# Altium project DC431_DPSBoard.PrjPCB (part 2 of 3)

## Sheet DC431_ADC.SchDoc
size C; Date: Not shown in title block; ApprovedBy: Not shown in title block; CheckedBy: Not shown in title block; Author: Not shown in title block; CompanyName: Not shown in title block; DrawnBy: Battery test; Engineer: Not shown in title block; Organization: Not shown in title block; Address1: Not shown in title block; Address2: Not shown in title block; Address3: Not shown in title block; Address4: Not shown in title block; DocumentNumber: 5; Revision: Use project parameter SCH_Rev; SheetNumber: 6; SheetTotal: 9; PageSetup: Record=PageOptions¦CenterHorizontal=True¦CenterVertical=True¦PrintScale=1.00¦XCorrection=1.00¦YCorrection=1.00¦PrintKind=0¦BorderSize=5000000¦LeftOffset=0¦BottomOffset=0¦Orientation=2¦PaperLength=1000¦PaperWidth=1000¦Scale=100¦PaperSource=15¦PrintQuality=600¦MediaType=1¦DitherType=10¦PaperKind=Letter¦PrintScaleMode=1
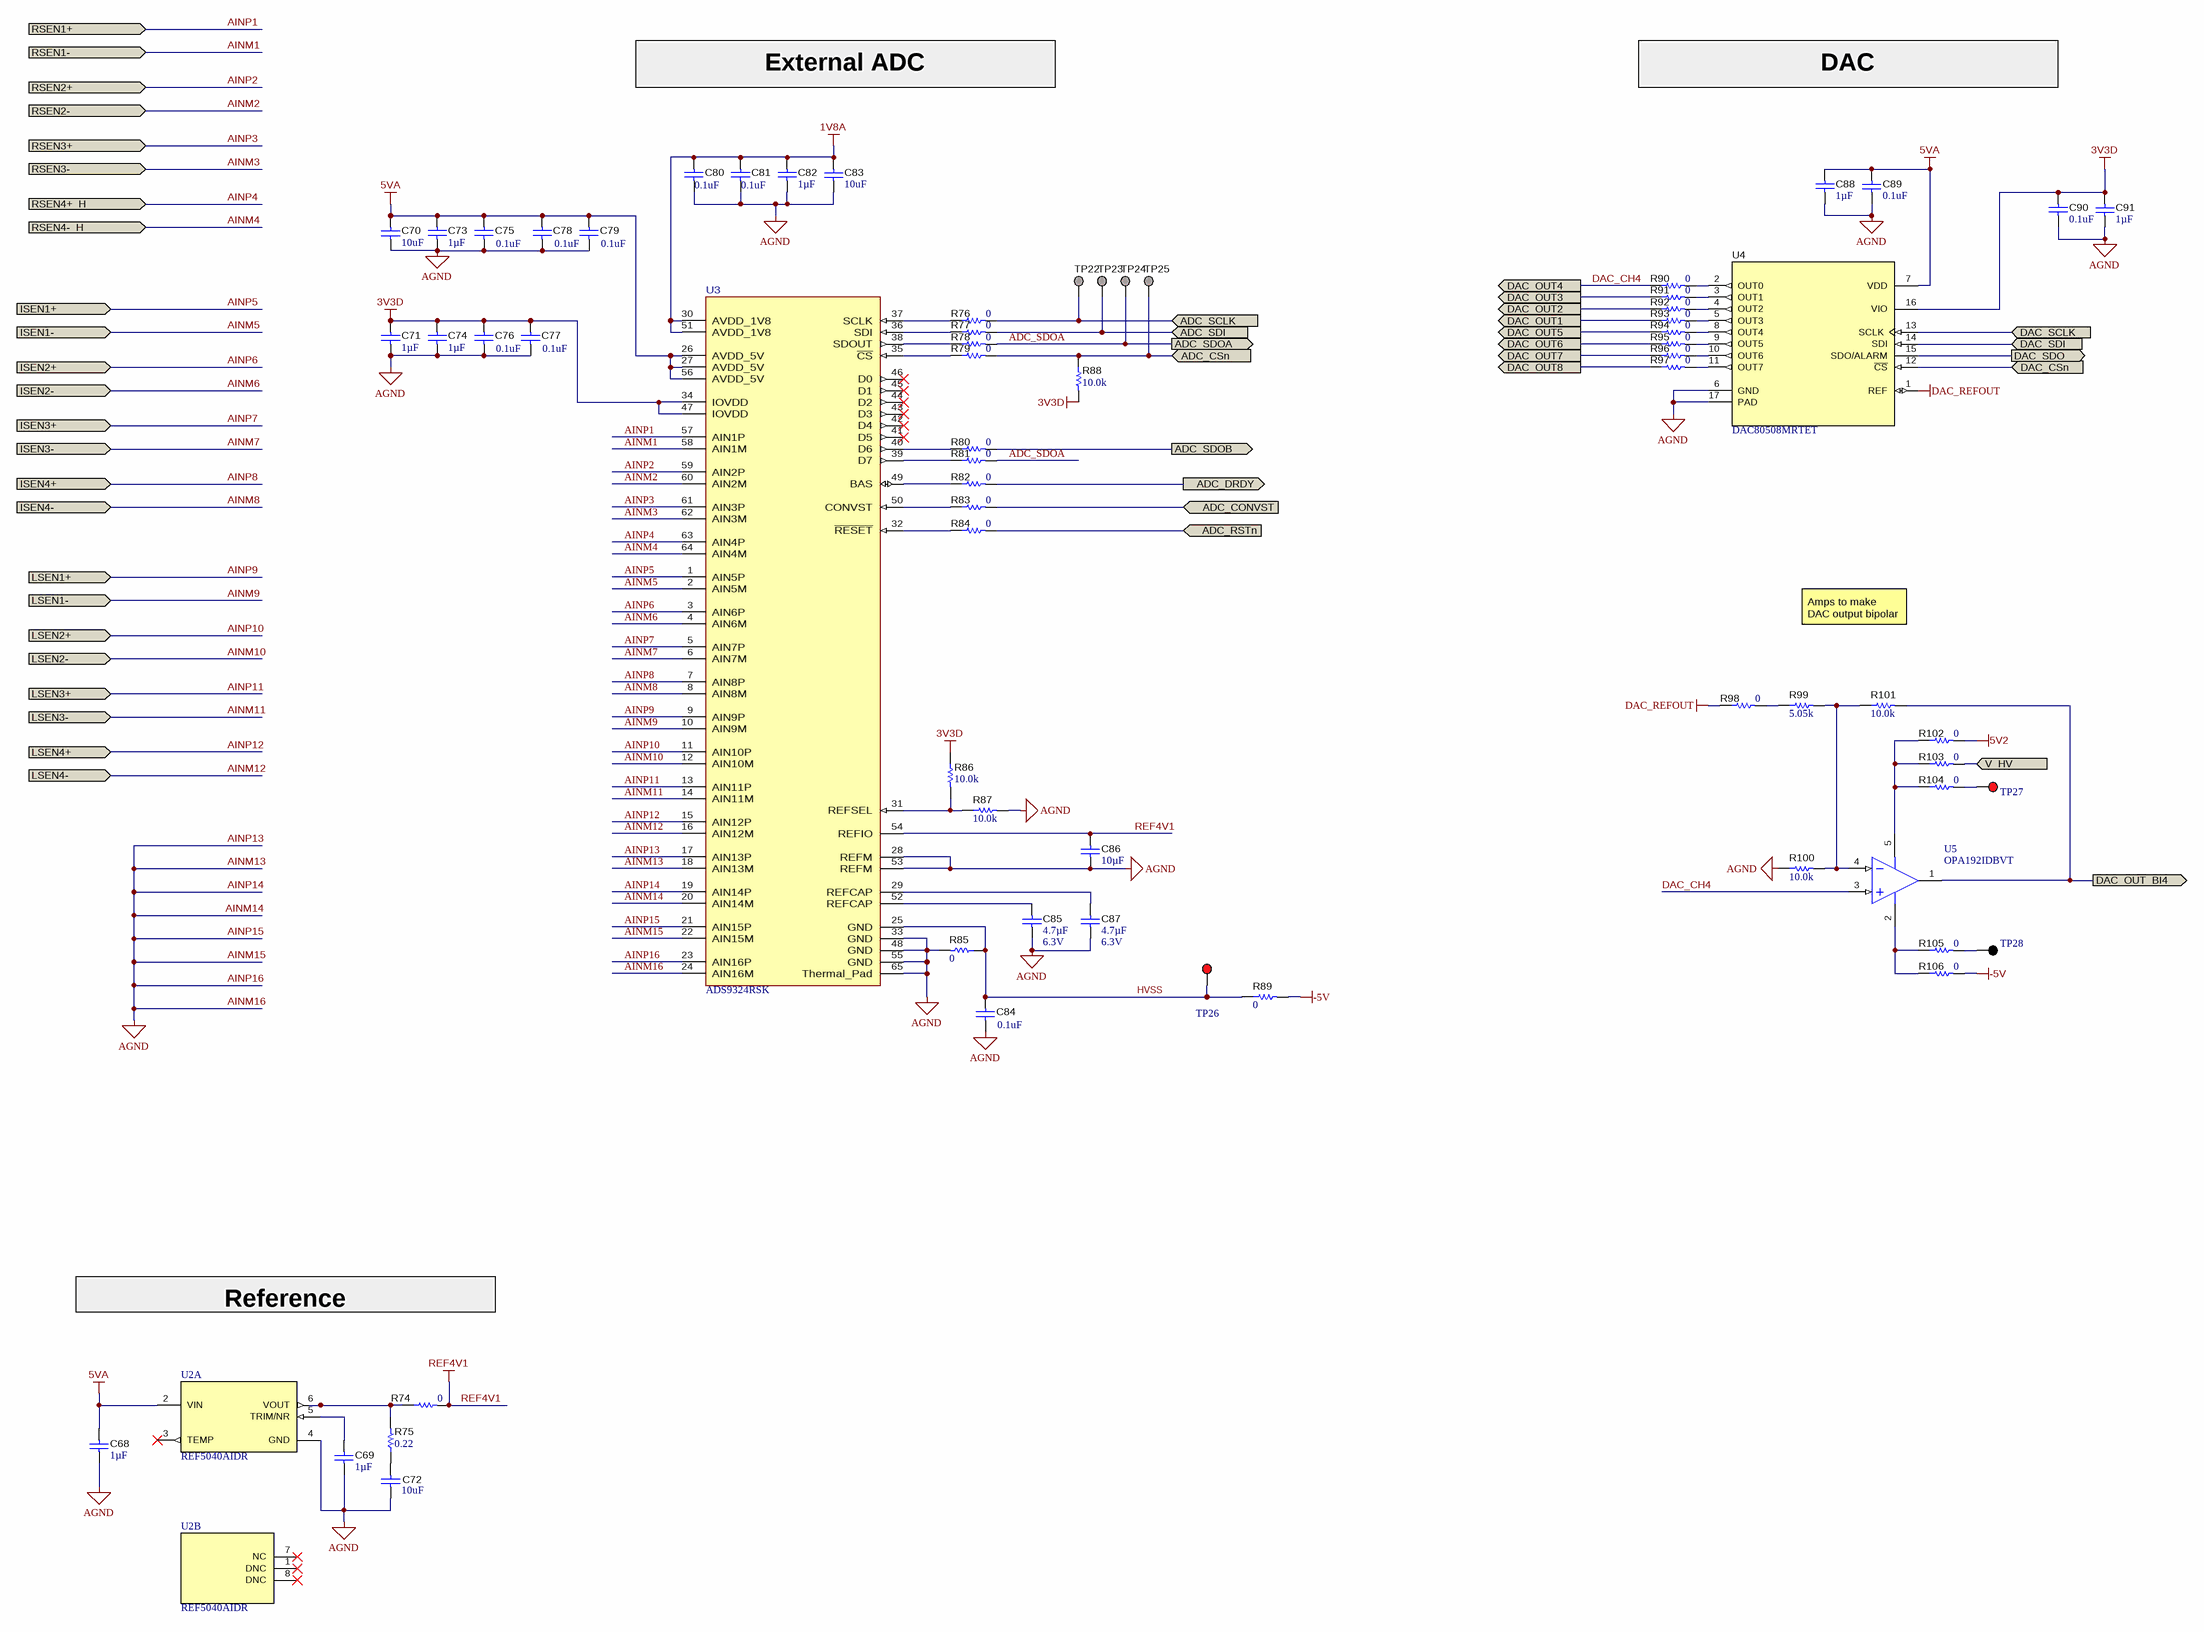
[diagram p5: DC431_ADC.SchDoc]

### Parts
C68  ValueDisplayed: 1µF  [0603S]  (hidden comment: CGA3E1X7R1E105K080AC)
C69  ValueDisplayed: 1µF  [0603S]  (hidden comment: CGA3E1X7R1E105K080AC)
C70  ValueDisplayed: 10uF  [0603S]  (hidden comment: GRM188R61E106MA73D)
C71  ValueDisplayed: 1µF  [0603S]  (hidden comment: CGA3E1X7R1E105K080AC)
C72  ValueDisplayed: 10uF  [0603S]  (hidden comment: GRM188R61E106MA73D)
C73  ValueDisplayed: 1µF  [0603S]  (hidden comment: CGA3E1X7R1E105K080AC)
C74  ValueDisplayed: 1µF  [0603S]  (hidden comment: CGA3E1X7R1E105K080AC)
C75  ValueDisplayed: 0.1uF  [0402S]  (hidden comment: GRM155R61C104KA88D)
C76  ValueDisplayed: 0.1uF  [0402S]  (hidden comment: GRM155R61C104KA88D)
C77  ValueDisplayed: 0.1uF  [0402S]  (hidden comment: GRM155R61C104KA88D)
C78  ValueDisplayed: 0.1uF  [0402S]  (hidden comment: GRM155R61C104KA88D)
C79  ValueDisplayed: 0.1uF  [0402S]  (hidden comment: GRM155R61C104KA88D)
C80  ValueDisplayed: 0.1uF  [0402S]  (hidden comment: GRM155R61C104KA88D)
C81  ValueDisplayed: 0.1uF  [0402S]  (hidden comment: GRM155R61C104KA88D)
C82  ValueDisplayed: 1µF  [0603S]  (hidden comment: CGA3E1X7R1E105K080AC)
C83  ValueDisplayed: 10uF  [0603S]  (hidden comment: GRM188R61E106MA73D)
C84  ValueDisplayed: 0.1uF  [0402S]  (hidden comment: GRM155R61C104KA88D)
C85  Cap_F: 4.7µF  VDC_V: 6.3V  [0201]  (hidden comment: GRM035R60J475ME15D)
C86  Cap_F: 10µF  [0603S]  (hidden comment: GRM188Z71A106MA73D)
C87  Cap_F: 4.7µF  VDC_V: 6.3V  [0201]  (hidden comment: GRM035R60J475ME15D)
C88  ValueDisplayed: 1µF  [0603S]  (hidden comment: CGA3E1X7R1E105K080AC)
C89  ValueDisplayed: 0.1uF  [0402S]  (hidden comment: GRM155R61C104KA88D)
C90  ValueDisplayed: 0.1uF  [0402S]  (hidden comment: GRM155R61C104KA88D)
C91  ValueDisplayed: 1µF  [0603S]  (hidden comment: CGA3E1X7R1E105K080AC)
R74  ValueDisplayed: 0  [0402S]  (hidden comment: CRCW04020000Z0ED)
R75  ValueDisplayed: 0.22  [0402S]  (hidden comment: ERJ-2BQFR22X)
R76  ValueDisplayed: 0  [0402S]  (hidden comment: CRCW04020000Z0ED)
R77  ValueDisplayed: 0  [0402S]  (hidden comment: CRCW04020000Z0ED)
R78  ValueDisplayed: 0  [0402S]  (hidden comment: CRCW04020000Z0ED)
R79  ValueDisplayed: 0  [0402S]  (hidden comment: CRCW04020000Z0ED)
R80  ValueDisplayed: 0  [0402S]  (hidden comment: CRCW04020000Z0ED)
R81  ValueDisplayed: 0  [0402S]  (hidden comment: CRCW04020000Z0ED)
R82  ValueDisplayed: 0  [0402S]  (hidden comment: CRCW04020000Z0ED)
R83  ValueDisplayed: 0  [0402S]  (hidden comment: CRCW04020000Z0ED)
R84  ValueDisplayed: 0  [0402S]  (hidden comment: CRCW04020000Z0ED)
R85  ValueDisplayed: 0  [0402S]  (hidden comment: CRCW04020000Z0ED)
R86  ValueDisplayed: 10.0k  [0603S]  (hidden comment: RT0603BRD0710KL)
R87  ValueDisplayed: 10.0k  [0603S]  (hidden comment: RT0603BRD0710KL)
R88  ValueDisplayed: 10.0k  [0603S]  (hidden comment: RT0603BRD0710KL)
R89  ValueDisplayed: 0  [0402S]  (hidden comment: CRCW04020000Z0ED)
R90  ValueDisplayed: 0  [0402S]  (hidden comment: CRCW04020000Z0ED)
R91  ValueDisplayed: 0  [0402S]  (hidden comment: CRCW04020000Z0ED)
R92  ValueDisplayed: 0  [0402S]  (hidden comment: CRCW04020000Z0ED)
R93  ValueDisplayed: 0  [0402S]  (hidden comment: CRCW04020000Z0ED)
R94  ValueDisplayed: 0  [0402S]  (hidden comment: CRCW04020000Z0ED)
R95  ValueDisplayed: 0  [0402S]  (hidden comment: CRCW04020000Z0ED)
R96  ValueDisplayed: 0  [0402S]  (hidden comment: CRCW04020000Z0ED)
R97  ValueDisplayed: 0  [0402S]  (hidden comment: CRCW04020000Z0ED)
R98  ValueDisplayed: 0  [0402S]  (hidden comment: CRCW04020000Z0ED)
R99  ValueDisplayed: 5.05k  [0603S]  (hidden comment: RT0603BRD075K05L)
R100  ValueDisplayed: 10.0k  [0603S]  (hidden comment: RT0603BRD0710KL)
R101  ValueDisplayed: 10.0k  [0603S]  (hidden comment: RT0603BRD0710KL)
R102  ValueDisplayed: 0  [0402S]  (hidden comment: CRCW04020000Z0ED)
R103  ValueDisplayed: 0  [0402S]  (hidden comment: CRCW04020000Z0ED)
R104  ValueDisplayed: 0  [0402S]  (hidden comment: CRCW04020000Z0ED)
R105  ValueDisplayed: 0  [0402S]  (hidden comment: CRCW04020000Z0ED)
R106  ValueDisplayed: 0  [0402S]  (hidden comment: CRCW04020000Z0ED)
TP22  TP_SM_1MM  [TP_SM_1MM]  (value not drawn)  (no BOM)
TP23  TP_SM_1MM  [TP_SM_1MM]  (value not drawn)  (no BOM)
TP24  TP_SM_1MM  [TP_SM_1MM]  (value not drawn)  (no BOM)
TP25  TP_SM_1MM  [TP_SM_1MM]  (value not drawn)  (no BOM)
TP26  5000  [Keystone5000]  (value not drawn)
TP27  5000  [Keystone5000]  (value not drawn)
TP28  5001  [Keystone5001]  (value not drawn)
U2  REF5040AIDR  [D0008A_N]  (parts A,B of 2)
U3  ADS9324RSK  [RSK0064B-MFG]
U4  DAC80508MRTET  [RTE0016D]
U5  OPA192IDBVT  [DBV0005A_N]

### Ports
ADC_CONVST (in), ADC_CSn (in), ADC_DRDY (out), ADC_RSTn (in), ADC_SCLK (in), ADC_SDI (in), ADC_SDOA (out), ADC_SDOB (out), DAC_CSn (in), DAC_OUT1 (out), DAC_OUT2 (out), DAC_OUT3 (out), DAC_OUT4 (out), DAC_OUT5 (out), DAC_OUT6 (out), DAC_OUT7 (out), DAC_OUT8 (out), DAC_OUT_BI4 (out), DAC_SCLK (in), DAC_SDI (in), DAC_SDO (out), ISEN1+ (in), ISEN1- (in), ISEN2+ (in), ISEN2- (in), ISEN3+ (in), ISEN3- (in), ISEN4+ (in), ISEN4- (in), LSEN1+ (in), LSEN1- (in), LSEN2+ (in), LSEN2- (in), LSEN3+ (in), LSEN3- (in), LSEN4+ (in), LSEN4- (in), RSEN1+ (in), RSEN1- (in), RSEN2+ (in), RSEN2- (in), RSEN3+ (in), RSEN3- (in), RSEN4+_H (in), RSEN4-_H (in), V_HV (in)

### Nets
1V8A: C80.2 C81.2 C82.2 C83.1 U3.30(AVDD_1V8) U3.51(AVDD_1V8)
3V3D: C71.2 C74.2 C76.2 C77.2 C90.1 C91.2 R86.1 R88.2 U3.34(IOVDD) U3.47(IOVDD) U4.16(VIO)
5V2: R102.2
5VA: C68.1 C70.1 C73.2 C75.2 C78.2 C79.2 C88.2 C89.1 U2.2(VIN) U3.26(AVDD_5V) U3.27(AVDD_5V) U3.56(AVDD_5V) U4.7(VDD)
-5V: R89.2 R106.2
AGND: C68.2 C69.2 C70.2 C71.1 C72.2 C73.1 C74.1 C75.1 C76.1 C77.1 C78.1 C79.1 C80.1 C81.1 C82.1 C83.2 C84.1 C85.2 C86.2 C87.2 C88.1 C89.2 C90.2 C91.1 R85.2 R87.2 R100.1 U2.4(GND) U3.17(AIN13P) U3.18(AIN13M) U3.19(AIN14P) U3.20(AIN14M) U3.21(AIN15P) U3.22(AIN15M) U3.23(AIN16P) U3.24(AIN16M) U3.28(REFM) U3.33(GND) U3.48(GND) U3.53(REFM) U3.55(GND) U3.65(Thermal_Pad) U4.6(GND) U4.17(PAD)  [also labelled AINM13, AINM14, AINM15, AINM16, AINP13, AINP14, AINP15, AINP16]
DAC_REFOUT: R98.1 U4.1(REF)
REF4V1: C86.1 R74.2 U3.54(REFIO)
ADC_CONVST: R83.2 ; port ADC_CONVST
ADC_CSn: R79.2 R88.1 TP25.1 ; port ADC_CSn
ADC_DRDY: R82.2 ; port ADC_DRDY
ADC_RSTn: R84.2 ; port ADC_RSTn
ADC_SCLK: R76.2 TP22.1 ; port ADC_SCLK
ADC_SDI: R77.2 TP23.1 ; port ADC_SDI
ADC_SDOA: R78.2 R81.2 TP24.1 ; port ADC_SDOA
ADC_SDOB: R80.2 ; port ADC_SDOB
AINM1: U3.58(AIN1M) ; port RSEN1-
AINM2: U3.60(AIN2M) ; port RSEN2-
AINM3: U3.62(AIN3M) ; port RSEN3-
AINM4: U3.64(AIN4M) ; port RSEN4-_H
AINM5: U3.2(AIN5M) ; port ISEN1-
AINM6: U3.4(AIN6M) ; port ISEN2-
AINM7: U3.6(AIN7M) ; port ISEN3-
AINM8: U3.8(AIN8M) ; port ISEN4-
AINM9: U3.10(AIN9M) ; port LSEN1-
AINM10: U3.12(AIN10M) ; port LSEN2-
AINM11: U3.14(AIN11M) ; port LSEN3-
AINM12: U3.16(AIN12M) ; port LSEN4-
AINP1: U3.57(AIN1P) ; port RSEN1+
AINP2: U3.59(AIN2P) ; port RSEN2+
AINP3: U3.61(AIN3P) ; port RSEN3+
AINP4: U3.63(AIN4P) ; port RSEN4+_H
AINP5: U3.1(AIN5P) ; port ISEN1+
AINP6: U3.3(AIN6P) ; port ISEN2+
AINP7: U3.5(AIN7P) ; port ISEN3+
AINP8: U3.7(AIN8P) ; port ISEN4+
AINP9: U3.9(AIN9P) ; port LSEN1+
AINP10: U3.11(AIN10P) ; port LSEN2+
AINP11: U3.13(AIN11P) ; port LSEN3+
AINP12: U3.15(AIN12P) ; port LSEN4+
DAC_CH4: R90.1 U5.3(IN+) ; port DAC_OUT4
DAC_CSn: U4.12(~{CS}) ; port DAC_CSn
DAC_OUT1: R93.1 ; port DAC_OUT1
DAC_OUT2: R92.1 ; port DAC_OUT2
DAC_OUT3: R91.1 ; port DAC_OUT3
DAC_OUT5: R94.1 ; port DAC_OUT5
DAC_OUT6: R95.1 ; port DAC_OUT6
DAC_OUT7: R96.1 ; port DAC_OUT7
DAC_OUT8: R97.1 ; port DAC_OUT8
DAC_OUT_BI4: R101.2 U5.1(OUT) ; port DAC_OUT_BI4
DAC_SCLK: U4.13(SCLK) ; port DAC_SCLK
DAC_SDI: U4.14(SDI) ; port DAC_SDI
DAC_SDO: U4.15(SDO/ALARM) ; port DAC_SDO
HVSS: C84.2 R85.1 R89.1 TP26.1 U3.25(GND)
V_HV: R103.2 ; port V_HV
NetC69_1: C69.1 U2.5(TRIM/NR)
NetC72_1: C72.1 R75.1
NetC85_1: C85.1 U3.52(REFCAP)
NetC87_1: C87.1 U3.29(REFCAP)
NetR74_1: R74.1 R75.2 U2.6(VOUT)
NetR76_1: R76.1 U3.37(SCLK)
NetR77_1: R77.1 U3.36(SDI)
NetR78_1: R78.1 U3.38(SDOUT)
NetR79_1: R79.1 U3.35(~{CS})
NetR80_1: R80.1 U3.40(D6)
NetR81_1: R81.1 U3.39(D7)
NetR82_1: R82.1 U3.49(BAS)
NetR83_1: R83.1 U3.50(CONVST)
NetR84_1: R84.1 U3.32(~{RESET})
NetR86_2: R86.2 R87.1 U3.31(REFSEL)
NetR90_2: R90.2 U4.2(OUT0)
NetR91_2: R91.2 U4.3(OUT1)
NetR92_2: R92.2 U4.4(OUT2)
NetR93_2: R93.2 U4.5(OUT3)
NetR94_2: R94.2 U4.8(OUT4)
NetR95_2: R95.2 U4.9(OUT5)
NetR96_2: R96.2 U4.10(OUT6)
NetR97_2: R97.2 U4.11(OUT7)
NetR98_2: R98.2 R99.1
NetR99_2: R99.2 R100.2 R101.1 U5.4(IN-)
NetR102_1: R102.1 R103.1 R104.1 U5.5(V+)
NetR104_2: R104.2 TP27.1
NetR105_1: R105.1 R106.1 U5.2(V-)
NetR105_2: R105.2 TP28.1

Not connected (* = marked no-connect by the designer): U2 1(DNC)* 3(TEMP)* 7(NC)* 8(DNC)*; U3 41(D5)* 42(D4)* 43(D3)* 44(D2)* 45(D1)* 46(D0)*

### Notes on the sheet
- External ADC
- DAC
- Amps to make DAC output bipolar
- Reference

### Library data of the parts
C68 C69 C71 C73 C74 C82 C88 C91 = CMP-0076705-3: CAP, CERM, 1 µF, 25 V,+/- 10%, X7R, AEC-Q200 Grade 1, 0603; Manufacturer: TDK; Polarized: N; Value: 1uF; U/M: EA; VDC_V: 25V; TaMin_C: -55°C; TaMax_C: 125°C; Cap_Case: 1.6x0.8x0.8mm; SizeAreaWB_mm2: 4.68; SizeArea_mm2: 1.28; AEC Qualified: Y; AEC Category: Q200; SizeZ_mm: 1.0; AEC Grade: 1; SizeY_mm: 0.8; SizeX_mm: 1.6
C70 C72 C83 = CMP-0007344-5: CAP, CERM, 10 uF, 25 V, +/- 20%, X5R, 0603; Manufacturer: MuRata; Polarized: N; Value: 10uF; U/M: EA; Cap_F: 10µF; Value1: Unknown; VDC_V: 25V; TaMin_C: -55°C; TaMax_C: 85°C; Cap_Case: 0603; SizeArea_mm2: 1.28; SizeAreaWB_mm2: 4.68; SizeX_mm: 1.6; SizeY_mm: 0.8; SizeZ_mm: 1; AEC Category: Q200
C75-C81 C84 C89 C90 = CMP-0006591-2: CAP, CERM, 0.1 uF, 16 V, +/- 10%, X5R, 0402; Manufacturer: MuRata; TaMin_C: -55°C; Polarized: N; SizeAreaWB_mm2: 3; Value1: Unknown; U/M: EA; Value: 0.1uF; TaMax_C: 85°C; SizeZ_mm: 0.6; SizeX_mm: 1; SizeY_mm: 0.5; Cap_Case: 0402; Value2: 16V; Cap_F: 100nF; AEC Category: Q200
C85 C87 = CMP-0009780-1: CAP, CERM, 4.7 uF, 6.3 V, +/- 20%, X5R, 0201; Manufacturer: MuRata; TaMin_C: -55°C; Polarized: N; SizeAreaWB_mm2: 2.08; Value1: Unknown; U/M: EA; Value: 4.7uF; TaMax_C: 85°C; SizeZ_mm: 0.26; SizeX_mm: 0.6; SizeY_mm: 0.3; SizeArea_mm2: 0.18; AEC Category: Q200
C86 = CMP-0007497-5: CAP, CERM, 10 uF, 10 V, +/- 20%, X7R, 0603; Manufacturer: MuRata; TaMin_C: -55°C; Polarized: N; SizeAreaWB_mm2: 4.68; Value1: Unknown; U/M: EA; Value: 10uF; TaMax_C: 125°C; SizeZ_mm: 1; SizeX_mm: 1.6; SizeY_mm: 0.8; Cap_Case: 0603; Value2: 10V; SizeArea_mm2: 1.28; AEC Category: Q200
R74 R76-R85 R89-R98 R102-R106 = CMP-0026822-3: RES, 0, 5%, 0.063 W, AEC-Q200 Grade 0, 0402; Manufacturer: Vishay-Dale; Value: 0; Value_Code: 0000; Power_W: 63mW; Value2: 0.063W; VDC_V: 50V; TempCo: 200 ppm/C; SizeArea_mm2: 0.5; SizeX_mm: 1; SizeZ_mm: 0.6; EIA_Code: E24; AEC Category: Q200; AEC Qualified: Y
R75 = CMP-0026632-2: RES, 0.22, 1%, 0.125 W, AEC-Q200 Grade 0, 0402; Manufacturer: Panasonic; Power_W: 125mW; TempCo: 250 ppm/C; Value_Code: R220; Value: 0.22; EIA_Code: E96; SizeX_mm: 1; SizeY_mm: 0.5; SizeZ_mm: 0.6; Value2: 0.125W; AEC Qualified: Y; AEC Category: Q200; AEC Grade: 0; SizeAreaWB_mm2: 3
R86-R88 = CMP-0023653-3: RES, 10.0 k, 0.1%, 0.1 W, 0603; Manufacturer: Yageo America; Power_W: 100mW; TempCo: 25 ppm/C; Value_Code: 10k0; Value: 10.0k; EIA_Code: E192; Res_ohm: 10k; SizeX_mm: 1.6; SizeY_mm: 0.8; SizeZ_mm: 1; Value2: 0.1W; SizeArea_mm2: 1.28; VDC_V: 75V; AEC Category: Q200; U/M: EA
R99 = CMP-0024365-1: RES, 5.05 k, 0.1%, 0.1 W, 0603; Manufacturer: Yageo America; Power_W: 100mW; TempCo: 25 ppm/C; Value_Code: 5k05; U/M: EA; Value: 5.05k; EIA_Code: E192; SizeX_mm: 1.6; SizeY_mm: 0.8; SizeZ_mm: 1; Value2: 0.1W; SizeArea_mm2: 1.28; VDC_V: 75V; AEC Category: Q200
R100 R101 = CMP-0023653-3: RES, 10.0 k, 0.1%, 0.1 W, 0603; Manufacturer: Yageo America; Power_W: 100mW; TempCo: 25 ppm/C; Value_Code: 10k0; U/M: EA; Value: 10.0k; EIA_Code: E192; Res_ohm: 10k; SizeX_mm: 1.6; SizeY_mm: 0.8; SizeZ_mm: 1; Value2: 0.1W; SizeArea_mm2: 1.28; VDC_V: 75V; AEC Category: Q200
TP22-TP25 = CMP-0003825-1: 1mm Test Point, SMT; Manufacturer: Any
TP26 TP27 = CMP-0055137-2: Test Point, Miniature, Red, TH; Manufacturer: Keystone Electronics; Green_REACh: Passed; Green_Lifecycle: Active; ContactFinish: Silver; CNHeader: FALSE; CT: TRUE
TP28 = CMP-0055138-2: Test Point, Miniature, Black, TH; Manufacturer: Keystone Electronics; CNHeader: FALSE; ContactFinish: Silver; Green_REACh: Passed; Green_Lifecycle: Active; CT: TRUE
U2 = CMP-0032601-1: Low Noise, Very Low Drift, Precision Voltage Reference, -40 to 125 degC, 8-pin SOIC (D), Green (RoHS & no Sb/Br); Manufacturer: Texas Instruments; Rating: Catalog; SubFamily: Series Voltage Reference; VI(Max)(V): 18; Temp Coeff(Max)(ppm/ degree C): 3; Initial Accuracy @ 25/deg C(%): 0.05; Iq(Max)(uA): 1000; VI(Min)(V): 4.296; Iout/Iz(Max)(mA): 10; VO(V): 4.096
U3 = CMP-0124125-1: 16-Channel, 16-Bit, 1-MSPS Simultaneous-Sampling SAR ADC with Bipolar Inputs on a Single Supply; Manufacturer: Texas Instruments; SizeZ_mm: 1mm; AEC Qualified: No; Data Polarity: Single Ended/Differential; Interface: SPI; Max Supply Voltage: 5.25V; Min Supply Voltage: 1.75V; Number Of Channels: 16; Resolution: 16bits; Sampling Rate: 1Msps; Standoff Height: 0mm; TaMax_C: +125°C; TaMin_C: -40°C; TJmax_C: +150°C
U4 = CMP-0084837-1: 8-Channel, True 16-Bit, SPI, Voltage-Output DAC With Precision Internal Reference, RTE0016D (WQFN-16); Manufacturer: Texas Instruments; Alternate PartNumber: DAC80508MRTER; SizeY_mm: 3; AEC Category: Q200; SizeAreaWB_mm2: 16; SizeArea_mm2: 9; AEC Qualified: N; SizeZ_mm: 0.8; CompType: IC; Rating: Catalog
U5 = CMP-0040539-2: Precision, Rail-to-Rail Input/Output, Low Offset Voltage, Low Input Bias Current Op Amp with E-trim, 4.5 to 36 V, -40 to 125 degC, 8-Pin SOT-23 (DBV), Green (RoHS & no Sb/Br), Tape and Reel; VS Max: 36 V; VS Min: 4.5 V; Channel: 1; Slew Rate: 20 V/us

## Sheet DC431_Controller.SchDoc
size 431 x 279 mm; Date: Not shown in title block; ApprovedBy: Not shown in title block; CheckedBy: Not shown in title block; Author: Not shown in title block; CompanyName: Not shown in title block; DrawnBy: Battery test; Engineer: Not shown in title block; Organization: Not shown in title block; Address1: Not shown in title block; Address2: Not shown in title block; Address3: Not shown in title block; Address4: Not shown in title block; DocumentNumber: 6; Revision: Use project parameter SCH_Rev; SheetNumber: 7; SheetTotal: 9; PageSetup: Record=PageOptions¦CenterHorizontal=True¦CenterVertical=True¦PrintScale=1.00¦XCorrection=1.00¦YCorrection=1.00¦PrintKind=0¦BorderSize=5000000¦LeftOffset=0¦BottomOffset=0¦Orientation=2¦PaperLength=1000¦PaperWidth=1000¦Scale=100¦PaperSource=15¦PrintQuality=600¦MediaType=1¦DitherType=10¦PaperKind=Letter¦PrintScaleMode=1
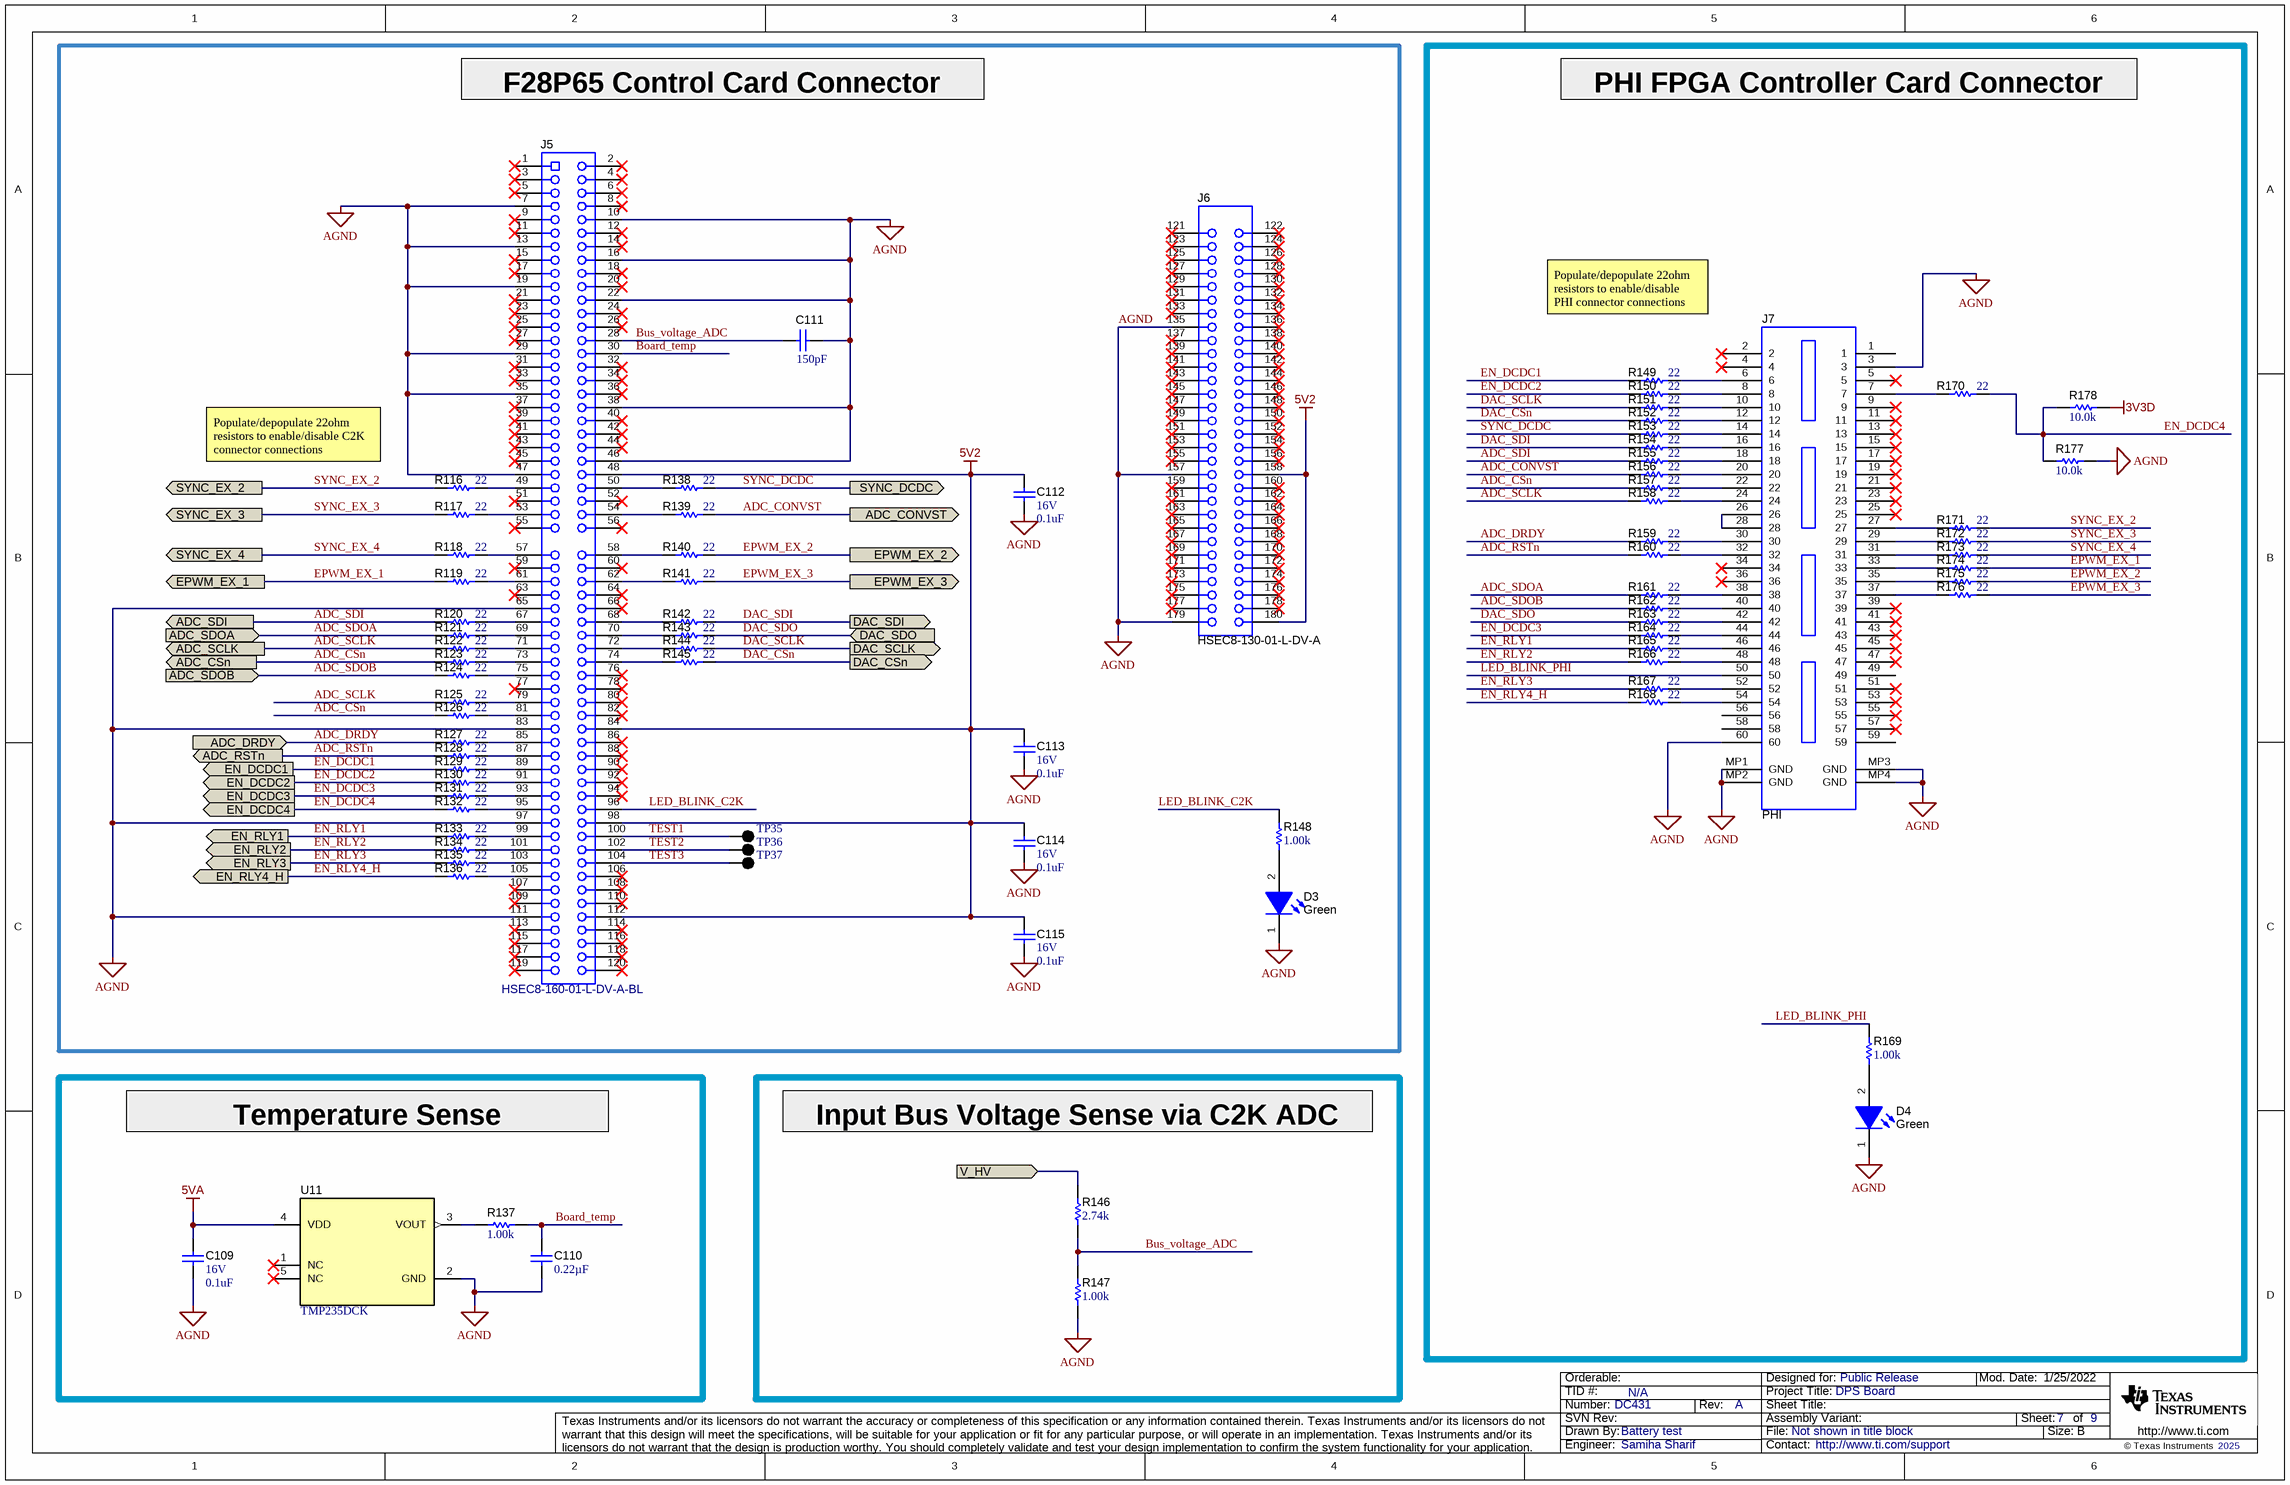
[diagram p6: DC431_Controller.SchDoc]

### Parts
C109  VDC_V: 16V  ValueDisplayed: 0.1uF  [0402S]  (hidden comment: GRM155R61C104KA88D)
C110  ValueDisplayed: 0.22µF  [0402S]  (hidden comment: GCM155R71C224KE02D)
C111  ValueDisplayed: 150pF  [0402S]  (hidden comment: GRM1555C1H151JA01D)
C112  VDC_V: 16V  ValueDisplayed: 0.1uF  [0402S]  (hidden comment: GRM155R61C104KA88D)
C113  VDC_V: 16V  ValueDisplayed: 0.1uF  [0402S]  (hidden comment: GRM155R61C104KA88D)
C114  VDC_V: 16V  ValueDisplayed: 0.1uF  [0402S]  (hidden comment: GRM155R61C104KA88D)
C115  VDC_V: 16V  ValueDisplayed: 0.1uF  [0402S]  (hidden comment: GRM155R61C104KA88D)
D3  value Green  [WL-SMCW_GREEN]  (hidden comment: 150060VS75000)
D4  value Green  [WL-SMCW_GREEN]  (hidden comment: 150060VS75000)
J5  HSEC8-160-01-L-DV-A-BL  [controlCARD-120HSEC]
J6  HSEC8-130-01-L-DV-A  [controlCARD-180HSEC-60pinAddon]
J7  PHI  [Samtec_QTH-030-01-x-D-A]
R116  ValueDisplayed: 22  [0402S]  (hidden comment: CRCW040222R0JNED)
R117  ValueDisplayed: 22  [0402S]  (hidden comment: CRCW040222R0JNED)
R118  ValueDisplayed: 22  [0402S]  (hidden comment: CRCW040222R0JNED)
R119  ValueDisplayed: 22  [0402S]  (hidden comment: CRCW040222R0JNED)
R120  ValueDisplayed: 22  [0402S]  (hidden comment: CRCW040222R0JNED)
R121  ValueDisplayed: 22  [0402S]  (hidden comment: CRCW040222R0JNED)
R122  ValueDisplayed: 22  [0402S]  (hidden comment: CRCW040222R0JNED)
R123  ValueDisplayed: 22  [0402S]  (hidden comment: CRCW040222R0JNED)
R124  ValueDisplayed: 22  [0402S]  (hidden comment: CRCW040222R0JNED)
R125  ValueDisplayed: 22  [0402S]  (hidden comment: CRCW040222R0JNED)
R126  ValueDisplayed: 22  [0402S]  (hidden comment: CRCW040222R0JNED)
R127  ValueDisplayed: 22  [0402S]  (hidden comment: CRCW040222R0JNED)
R128  ValueDisplayed: 22  [0402S]  (hidden comment: CRCW040222R0JNED)
R129  ValueDisplayed: 22  [0402S]  (hidden comment: CRCW040222R0JNED)
R130  ValueDisplayed: 22  [0402S]  (hidden comment: CRCW040222R0JNED)
R131  ValueDisplayed: 22  [0402S]  (hidden comment: CRCW040222R0JNED)
R132  ValueDisplayed: 22  [0402S]  (hidden comment: CRCW040222R0JNED)
R133  ValueDisplayed: 22  [0402S]  (hidden comment: CRCW040222R0JNED)
R134  ValueDisplayed: 22  [0402S]  (hidden comment: CRCW040222R0JNED)
R135  ValueDisplayed: 22  [0402S]  (hidden comment: CRCW040222R0JNED)
R136  ValueDisplayed: 22  [0402S]  (hidden comment: CRCW040222R0JNED)
R137  ValueDisplayed: 1.00k  [0402S]  (hidden comment: ERA-2AEB102X)
R138  ValueDisplayed: 22  [0402S]  (hidden comment: CRCW040222R0JNED)
R139  ValueDisplayed: 22  [0402S]  (hidden comment: CRCW040222R0JNED)
R140  ValueDisplayed: 22  [0402S]  (hidden comment: CRCW040222R0JNED)
R141  ValueDisplayed: 22  [0402S]  (hidden comment: CRCW040222R0JNED)
R142  ValueDisplayed: 22  [0402S]  (hidden comment: CRCW040222R0JNED)
R143  ValueDisplayed: 22  [0402S]  (hidden comment: CRCW040222R0JNED)
R144  ValueDisplayed: 22  [0402S]  (hidden comment: CRCW040222R0JNED)
R145  ValueDisplayed: 22  [0402S]  (hidden comment: CRCW040222R0JNED)
R146  ValueDisplayed: 2.74k  [0402S]  (hidden comment: PCF0402-12-2K74BT1)
R147  ValueDisplayed: 1.00k  [0402S]  (hidden comment: ERA-2AEB102X)
R148  ValueDisplayed: 1.00k  [0402S]  (hidden comment: ERA-2AEB102X)
R149  ValueDisplayed: 22  [0402S]  (hidden comment: CRCW040222R0JNED)
R150  ValueDisplayed: 22  [0402S]  (hidden comment: CRCW040222R0JNED)
R151  ValueDisplayed: 22  [0402S]  (hidden comment: CRCW040222R0JNED)
R152  ValueDisplayed: 22  [0402S]  (hidden comment: CRCW040222R0JNED)
R153  ValueDisplayed: 22  [0402S]  (hidden comment: CRCW040222R0JNED)
R154  ValueDisplayed: 22  [0402S]  (hidden comment: CRCW040222R0JNED)
R155  ValueDisplayed: 22  [0402S]  (hidden comment: CRCW040222R0JNED)
R156  ValueDisplayed: 22  [0402S]  (hidden comment: CRCW040222R0JNED)
R157  ValueDisplayed: 22  [0402S]  (hidden comment: CRCW040222R0JNED)
R158  ValueDisplayed: 22  [0402S]  (hidden comment: CRCW040222R0JNED)
R159  ValueDisplayed: 22  [0402S]  (hidden comment: CRCW040222R0JNED)
R160  ValueDisplayed: 22  [0402S]  (hidden comment: CRCW040222R0JNED)
R161  ValueDisplayed: 22  [0402S]  (hidden comment: CRCW040222R0JNED)
R162  ValueDisplayed: 22  [0402S]  (hidden comment: CRCW040222R0JNED)
R163  ValueDisplayed: 22  [0402S]  (hidden comment: CRCW040222R0JNED)
R164  ValueDisplayed: 22  [0402S]  (hidden comment: CRCW040222R0JNED)
R165  ValueDisplayed: 22  [0402S]  (hidden comment: CRCW040222R0JNED)
R166  ValueDisplayed: 22  [0402S]  (hidden comment: CRCW040222R0JNED)
R167  ValueDisplayed: 22  [0402S]  (hidden comment: CRCW040222R0JNED)
R168  ValueDisplayed: 22  [0402S]  (hidden comment: CRCW040222R0JNED)
R169  ValueDisplayed: 1.00k  [0402S]  (hidden comment: ERA-2AEB102X)
R170  ValueDisplayed: 22  [0402S]  (hidden comment: CRCW040222R0JNED)
R171  ValueDisplayed: 22  [0402S]  (hidden comment: CRCW040222R0JNED)
R172  ValueDisplayed: 22  [0402S]  (hidden comment: CRCW040222R0JNED)
R173  ValueDisplayed: 22  [0402S]  (hidden comment: CRCW040222R0JNED)
R174  ValueDisplayed: 22  [0402S]  (hidden comment: CRCW040222R0JNED)
R175  ValueDisplayed: 22  [0402S]  (hidden comment: CRCW040222R0JNED)
R176  ValueDisplayed: 22  [0402S]  (hidden comment: CRCW040222R0JNED)
R177  value 10.0k  [0402S]  (hidden comment: CRCW040210K0FKED)
R178  value 10.0k  [0402S]  (hidden comment: CRCW040210K0FKED)
TP35  5001  [Keystone5001]  (value not drawn)
TP36  5001  [Keystone5001]  (value not drawn)
TP37  5001  [Keystone5001]  (value not drawn)
U11  TMP235DCK  [DCK0005A_N]

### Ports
ADC_CONVST (out), ADC_CSn (out), ADC_DRDY (in), ADC_RSTn (out), ADC_SCLK (out), ADC_SDI (out), ADC_SDOA (in), ADC_SDOB (in), DAC_CSn (out), DAC_SCLK (out), DAC_SDI (out), DAC_SDO (in), EN_DCDC1 (out), EN_DCDC2 (out), EN_DCDC3 (out), EN_DCDC4 (out), EN_RLY1 (out), EN_RLY2 (out), EN_RLY3 (out), EN_RLY4_H (out), EPWM_EX_1 (out), EPWM_EX_2 (out), EPWM_EX_3 (out), SYNC_DCDC (out), SYNC_EX_2 (out), SYNC_EX_3 (out), SYNC_EX_4 (out), V_HV (in)

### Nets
3V3D: R178.2
5V2: C112.2 C113.2 C114.2 C115.2 J5.48 J5.84 J5.98 J5.112 J6.158 J6.180
5VA: C109.2 U11.4(VDD)
AGND: C109.1 C110.2 C111.1 C112.1 C113.1 C114.1 C115.1 D3.1(K) D4.1(K) J5.7 J5.10 J5.13 J5.16 J5.19 J5.22 J5.29 J5.35 J5.38 J5.46 J5.47 J5.65 J5.83 J5.97 J5.111 J6.135 J6.157 J6.179 J7.3 J7.60 J7.MP1(GND) J7.MP2(GND) J7.MP3(GND) J7.MP4(GND) R147.2 R177.1 U11.2(GND)
ADC_CONVST: R139.2 R156.1 ; port ADC_CONVST
ADC_CSn: R123.1 R126.1 R157.1 ; port ADC_CSn
ADC_DRDY: R127.1 R159.1 ; port ADC_DRDY
ADC_RSTn: R128.1 R160.1 ; port ADC_RSTn
ADC_SCLK: R122.1 R125.1 R158.1 ; port ADC_SCLK
ADC_SDI: R120.1 R155.1 ; port ADC_SDI
ADC_SDOA: R121.1 R161.1 ; port ADC_SDOA
ADC_SDOB: R124.1 R162.1 ; port ADC_SDOB
Board_temp: C110.1 J5.30 R137.1
Bus_voltage_ADC: C111.2 J5.28 R146.1 R147.1
DAC_CSn: R145.2 R152.1 ; port DAC_CSn
DAC_SCLK: R144.2 R151.1 ; port DAC_SCLK
DAC_SDI: R142.2 R154.1 ; port DAC_SDI
DAC_SDO: R143.2 R163.1 ; port DAC_SDO
EN_DCDC1: R129.1 R149.1 ; port EN_DCDC1
EN_DCDC2: R130.1 R150.1 ; port EN_DCDC2
EN_DCDC3: R131.1 R164.1 ; port EN_DCDC3
EN_DCDC4: R132.1 R170.2 R177.2 R178.1 ; port EN_DCDC4
EN_RLY1: R133.1 R165.1 ; port EN_RLY1
EN_RLY2: R134.1 R166.1 ; port EN_RLY2
EN_RLY3: R135.1 R167.1 ; port EN_RLY3
EN_RLY4_H: R136.1 R168.1 ; port EN_RLY4_H
EPWM_EX_1: R119.1 R174.2 ; port EPWM_EX_1
EPWM_EX_2: R140.2 R175.2 ; port EPWM_EX_2
EPWM_EX_3: R141.2 R176.2 ; port EPWM_EX_3
LED_BLINK_C2K: J5.96 R148.2
LED_BLINK_PHI: J7.50 R169.2
SYNC_DCDC: R138.2 R153.1 ; port SYNC_DCDC
SYNC_EX_2: R116.1 R171.2 ; port SYNC_EX_2
SYNC_EX_3: R117.1 R172.2 ; port SYNC_EX_3
SYNC_EX_4: R118.1 R173.2 ; port SYNC_EX_4
TEST1: J5.100 TP35.1
TEST2: J5.102 TP36.1
TEST3: J5.104 TP37.1
V_HV: R146.2 ; port V_HV
NetD3_2: D3.2(A) R148.1
NetD4_2: D4.2(A) R169.1
NetJ5_49: J5.49 R116.2
NetJ5_50: J5.50 R138.1
NetJ5_53: J5.53 R117.2
NetJ5_54: J5.54 R139.1
NetJ5_57: J5.57 R118.2
NetJ5_58: J5.58 R140.1
NetJ5_61: J5.61 R119.2
NetJ5_62: J5.62 R141.1
NetJ5_67: J5.67 R120.2
NetJ5_68: J5.68 R142.1
NetJ5_69: J5.69 R121.2
NetJ5_70: J5.70 R143.1
NetJ5_71: J5.71 R122.2
NetJ5_72: J5.72 R144.1
NetJ5_73: J5.73 R123.2
NetJ5_74: J5.74 R145.1
NetJ5_75: J5.75 R124.2
NetJ5_79: J5.79 R125.2
NetJ5_81: J5.81 R126.2
NetJ5_85: J5.85 R127.2
NetJ5_87: J5.87 R128.2
NetJ5_89: J5.89 R129.2
NetJ5_91: J5.91 R130.2
NetJ5_93: J5.93 R131.2
NetJ5_95: J5.95 R132.2
NetJ5_99: J5.99 R133.2
NetJ5_101: J5.101 R134.2
NetJ5_103: J5.103 R135.2
NetJ5_105: J5.105 R136.2
NetJ7_6: J7.6 R149.2
NetJ7_7: J7.7 R170.1
NetJ7_8: J7.8 R150.2
NetJ7_10: J7.10 R151.2
NetJ7_12: J7.12 R152.2
NetJ7_14: J7.14 R153.2
NetJ7_16: J7.16 R154.2
NetJ7_18: J7.18 R155.2
NetJ7_20: J7.20 R156.2
NetJ7_22: J7.22 R157.2
NetJ7_24: J7.24 R158.2
NetJ7_26: J7.26 J7.28
NetJ7_27: J7.27 R171.1
NetJ7_29: J7.29 R172.1
NetJ7_30: J7.30 R159.2
NetJ7_31: J7.31 R173.1
NetJ7_32: J7.32 R160.2
NetJ7_33: J7.33 R174.1
NetJ7_35: J7.35 R175.1
NetJ7_37: J7.37 R176.1
NetJ7_38: J7.38 R161.2
NetJ7_40: J7.40 R162.2
NetJ7_42: J7.42 R163.2
NetJ7_44: J7.44 R164.2
NetJ7_46: J7.46 R165.2
NetJ7_48: J7.48 R166.2
NetJ7_52: J7.52 R167.2
NetJ7_54: J7.54 R168.2
NetR137_2: R137.2 U11.3(VOUT)

Not connected (* = marked no-connect by the designer): J5 1* 2* 3* 4* 5* 6* 8* 9* 11* 12* 14* 15* 17* 18* 20* 21* 23* 24* 25* 26* 27* 31* 32* 33* 34* 36* 37* 39* 40* 41* 42* 43* 44* 45* 51* 52* 55* 56* 59* 60* 63* 64* 66* 76* 77* 78* 80* 82* 86* 88* 90* 92* 94* 106* 107* 108* 109* 110* 113* 114* 115* 116* 117* 118* 119* 120*; J6 121* 122* 123* 124* 125* 126* 127* 128* 129* 130* 131* 132* 133* 134* 136* 137* 138* 139* 140* 141* 142* 143* 144* 145* 146* 147* 148* 149* 150* 151* 152* 153* 154* 155* 156* 159* 160* 161* 162* 163* 164* 165* 166* 167* 168* 169* 170* 171* 172* 173* 174* 175* 176* 177* 178*; J7 1 2* 4* 5* 9* 11* 13* 15* 17* 19* 21* 23* 25* 34* 36* 39* 41* 43* 45* 47* 49 51* 53* 55* 56 57* 58 59; U11 1(NC)* 5(NC)*

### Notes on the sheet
- F28P65 Control Card Connector
- PHI FPGA Controller Card Connector
- Populate/depopulate 22ohm resistors to enable/disable PHI connector connections
- Populate/depopulate 22ohm resistors to enable/disable C2K connector connections
- Temperature Sense
- Input Bus Voltage Sense via C2K ADC

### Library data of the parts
C109 C112-C115 = CMP-0006591-2: CAP, CERM, 0.1 uF, 16 V, +/- 10%, X5R, 0402; Manufacturer: MuRata; TaMin_C: -55°C; Polarized: N; SizeAreaWB_mm2: 3; Value1: Unknown; U/M: EA; Value: 0.1uF; TaMax_C: 85°C; SizeZ_mm: 0.6; SizeX_mm: 1; SizeY_mm: 0.5; Cap_Case: 0402; Cap_F: 100nF; AEC Category: Q200
C110 = CMP-0078265-1: CAP, CERM, 0.22 µF, 16 V,+/- 10%, X7R, AEC-Q200 Grade 1, 0402; Manufacturer: MuRata; TaMin_C: -55°C; Polarized: N; SizeAreaWB_mm2: 3; U/M: EA; Value: 0.22uF; TaMax_C: 125°C; SizeZ_mm: 0.6; SizeX_mm: 1; SizeY_mm: 0.5; Cap_Case: 0402; Value2: 16V; AEC Qualified: Y; Cap_F: 220nF; AEC Category: Q200
C111 = CMP-0006421-1: CAP, CERM, 150 pF, 50 V, +/- 5%, C0G/NP0, 0402; Manufacturer: MuRata; TaMin_C: -55°C; Polarized: N; SizeAreaWB_mm2: 3; Value1: Unknown; U/M: EA; Value: 150pF; TaMax_C: 125°C; SizeZ_mm: 0.6; SizeX_mm: 1; SizeY_mm: 0.5; Cap_Case: 0402; Value2: 50V; AEC Category: Q200
D3 D4 = CMP-0002894-2: LED, Green, SMD; Manufacturer: Wurth Elektronik; Type: AlInGaP; Vf_V: 2V; Io_A: 20mA; Value1: W
J5 = CMP-0003814-2: C2000 controlCARD-120HSEC connector, SMT; Manufacturer: Samtec; Note: The pin numbering does not match Samtec datasheet
J6 = CMP-0003859-2: C2000 controlCARD-180HSEC (60-pin addon) connector, SMT; Manufacturer: Samtec; Note: The pin numbering does not match Samtec datasheet
J7 = CMP-0075558-2: Header(Shrouded), 19.7mil, 30x2, Gold, SMT; PartNumber: QTH-030-01-L-D-A; Manufacturer: Samtec; Pitch_mm: 0.5; Gender: Male; Green_REACh: Passed; CT: False; Shrouded: Y; Green_Lifecycle: Active; Row_Count: 2
R116-R136 R138-R145 = CMP-0026880-3: RES, 22, 5%, 0.063 W, AEC-Q200 Grade 0, 0402; Manufacturer: Vishay-Dale; Power_W: 63mW; TempCo: 200 ppm/C; Value_Code: 22R0; Value: 22; EIA_Code: E24; SizeX_mm: 1; SizeY_mm: 0.5; SizeZ_mm: 0.6; Value2: 0.063W; AEC Qualified: Y; VDC_V: 50V; AEC Category: Q200; AEC Grade: 0
R137 R147 R148 R169 = CMP-0026770-1: RES, 1.00 k, 0.1%, 0.063 W, 0402; Manufacturer: Panasonic; Power_W: 63mW; TempCo: 25 ppm/C; Value_Code: 1k00; U/M: EA; Value: 1.00k; EIA_Code: E192; Res_ohm: 1k; SizeX_mm: 1; SizeY_mm: 0.5; SizeZ_mm: 0.6; Value2: 0.063W; VDC_V: 50V; AEC Category: Q200
R146 = CMP-0026805-1: RES, 2.74 k, 0.1%, 0.063 W, 0402; Manufacturer: TT Electronics/IRC; Power_W: 63mW; TempCo: 10 ppm/C; Value_Code: 2k74; U/M: EA; Value: 2.74k; EIA_Code: E192; SizeX_mm: 1; SizeY_mm: 0.5; SizeZ_mm: 0.6; Value2: 0.063W; AEC Qualified: N; VDC_V: 25V; AEC Category: Q200
R149-R168 R170-R176 = CMP-0026880-3: RES, 22, 5%, 0.063 W, AEC-Q200 Grade 0, 0402; Manufacturer: Vishay-Dale; Power_W: 63mW; TempCo: 200 ppm/C; Value_Code: 22R0; Value: 22; SizeX_mm: 1; SizeY_mm: 0.5; SizeZ_mm: 0.6; Value2: 0.063W; AEC Qualified: Y; VDC_V: 50V; AEC Category: Q200; AEC Grade: 0; EIA_Code: E24
R177 R178 = CMP-0025958-3: RES, 10.0 k, 1%, 0.063 W, AEC-Q200 Grade 0, 0402; Manufacturer: Vishay-Dale; VDC_V: 50V; SizeZ_mm: 0.6; Res_ohm: 10k; TempCo: 100 ppm/C; Power_W: 63mW; AEC Qualified: Y; Value_Code: 10k0; EIA_Code: E96; SizeX_mm: 1; SizeY_mm: 0.5; Value2: 0.063W; AEC Category: Q200; AEC Grade: 0
TP35-TP37 = CMP-0055138-2: Test Point, Miniature, Black, TH; Manufacturer: Keystone Electronics; ContactFinish: Silver; Green_Lifecycle: Active; Green_REACh: Passed; CNHeader: FALSE; CT: TRUE
U11 = CMP-0013250-3: TMP235DCK, DCK0005A (SOT-5); Manufacturer: Texas Instruments; SizeX_mm: 2.1; SizeY_mm: 2.0; CompType: IC; SizeZ_mm: 1.1; SizeArea_mm2: 4.2; SizeAreaWB_mm2: 9.3; AEC Category: Q200; AEC Qualified: N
